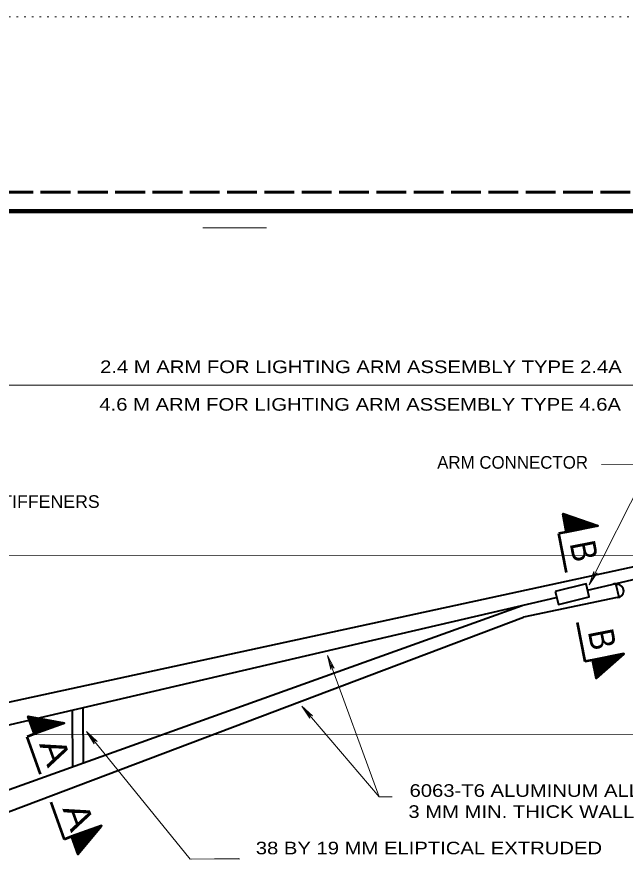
# Model space of a CAD drawing. Extents: x 312583 to 312854, y 144419 to 144597.
# Drawn here: x 312778.8 to 312815.4, y 144545.9 to 144596.8 of the extents above; entities that cross this region are included whole.
import ezdxf
from ezdxf.enums import TextEntityAlignment as Align

# ---------------------------------------------------------------- set-up
doc = ezdxf.new("R2010")
doc.units = 0
doc.header["$LTSCALE"] = 0.3
doc.linetypes.add('DOTTED', pattern=[1.5, 0.3, -1.2])
doc.linetypes.add('LONG_DASHED', pattern=[7.5, 6, -1.5])
for name, color, linetype, lineweight in [('1', 7, 'Continuous', 35), ('2', 7, 'Continuous', 13), ('62', 7, 'DOTTED', 13), ('63', 7, 'LONG_DASHED', 60)]:
    doc.layers.add(name, color=color, linetype=linetype, lineweight=lineweight)

msp = doc.modelspace()

# ---------------------------------------------------------------- linework, layer by layer
at = {"layer": '1', "lineweight": 13}
msp.add_line((312793.8154, 144584.0756), (312789.9897, 144584.0756), dxfattribs=at)
at = {"layer": '1'}
for p, q in [((312811.7094, 144566.8026), (312811.7247, 144566.8256)), ((312811.717, 144566.7643), (312811.7477, 144566.818)), ((312811.7324, 144566.7106), (312811.763, 144566.8103)), ((312811.74, 144566.6646), (312811.7937, 144566.795)), ((312811.7477, 144566.611), (312811.8167, 144566.795)), ((312811.7554, 144566.5726), (312811.832, 144566.7796)), ((312811.763, 144566.519), (312811.855, 144566.7796)), ((312811.7784, 144566.473), (312811.8857, 144566.772)), ((312811.786, 144566.427), (312811.901, 144566.7643)), ((312811.7937, 144566.381), (312811.9317, 144566.7566)), ((312811.8014, 144566.335), (312811.947, 144566.749)), ((312811.809, 144566.289), (312811.97, 144566.7413)), ((312811.8244, 144566.243), (312812.0007, 144566.7336)), ((312811.832, 144566.1893), (312812.016, 144566.726)), ((312811.8397, 144566.1433), (312812.039, 144566.7183)), ((312811.8474, 144566.0973), (312812.0544, 144566.7106)), ((312811.855, 144566.0436), (312812.085, 144566.6953)), ((312811.8704, 144565.9976), (312812.108, 144566.6953)), ((312811.878, 144565.9516), (312812.1234, 144566.68)), ((312811.8857, 144565.9133), (312812.154, 144566.6723)), ((312811.8934, 144565.8596), (312812.177, 144566.6723)), ((312811.901, 144565.8213), (312812.1924, 144566.657)), ((312811.9164, 144565.7676), (312812.223, 144566.657)), ((312811.9317, 144565.7446), (312812.2384, 144566.6416)), ((312811.9624, 144565.7523), (312812.269, 144566.6416)), ((312811.993, 144565.76), (312812.292, 144566.6263)), ((312812.016, 144565.7676), (312812.3074, 144566.6263)), ((312812.0467, 144565.7676), (312812.3304, 144566.611)), ((312812.062, 144565.783), (312812.361, 144566.611)), ((312812.0927, 144565.7906), (312812.3764, 144566.5956)), ((312812.1234, 144565.783), (312812.3994, 144566.5956)), ((312812.1464, 144565.7906), (312812.4224, 144566.588)), ((312812.177, 144565.7983), (312812.4454, 144566.5726)), ((312812.2, 144565.7983), (312812.4684, 144566.5726)), ((312812.2307, 144565.806), (312812.4914, 144566.5573)), ((312812.2614, 144565.8136), (312812.522, 144566.5496)), ((312812.2844, 144565.8136), (312812.5374, 144566.542)), ((312812.315, 144565.829), (312812.5604, 144566.5343)), ((312812.3457, 144565.829), (312812.5834, 144566.5266)), ((312812.3687, 144565.829), (312812.5987, 144566.519)), ((312812.3917, 144565.8366), (312812.6294, 144566.519)), ((312812.4224, 144565.8443), (312812.6524, 144566.5036)), ((312812.453, 144565.852), (312812.6677, 144566.5036)), ((312812.4837, 144565.852), (312812.6907, 144566.4883)), ((312812.5067, 144565.8596), (312812.7137, 144566.4883)), ((312812.5374, 144565.8673), (312812.7367, 144566.473)), ((312812.5527, 144565.875), (312812.7674, 144566.473)), ((312812.591, 144565.875), (312812.7827, 144566.4576)), ((312812.6064, 144565.8826), (312812.8134, 144566.45)), ((312812.637, 144565.8826), (312812.8364, 144566.4423)), ((312812.6677, 144565.8903), (312812.8517, 144566.4346)), ((312812.6907, 144565.898), (312812.8747, 144566.4346)), ((312812.7214, 144565.898), (312812.9054, 144566.4193)), ((312812.752, 144565.9056), (312812.9207, 144566.4193)), ((312812.775, 144565.9133), (312812.9437, 144566.404)), ((312812.8057, 144565.9133), (312812.9667, 144566.404)), ((312812.8364, 144565.921), (312812.9897, 144566.3886)), ((312812.8594, 144565.9286), (312813.0127, 144566.3886)), ((312812.8824, 144565.9286), (312813.0357, 144566.3733)), ((312812.913, 144565.9363), (312813.0587, 144566.3733)), ((312812.9437, 144565.944), (312813.0817, 144566.358)), ((312812.9667, 144565.9516), (312813.1047, 144566.3503)), ((312812.9897, 144565.9516), (312813.1277, 144566.3503)), ((312813.0204, 144565.9593), (312813.143, 144566.335)), ((312813.0434, 144565.967), (312813.1737, 144566.3273)), ((312813.074, 144565.967), (312813.1967, 144566.3196)), ((312813.097, 144565.9746), (312813.212, 144566.312)), ((312813.1277, 144565.9823), (312813.235, 144566.3043)), ((312813.1584, 144565.99), (312813.2657, 144566.2966)), ((312813.1814, 144565.99), (312813.281, 144566.289)), ((312813.212, 144565.9976), (312813.3117, 144566.2813)), ((312813.235, 144565.9976), (312813.327, 144566.2736)), ((312813.2657, 144566.0053), (312813.3577, 144566.266)), ((312813.2964, 144566.013), (312813.3807, 144566.266)), ((312813.3194, 144566.0206), (312813.396, 144566.2506)), ((312813.35, 144566.0206), (312813.419, 144566.2506)), ((312813.3654, 144566.0283), (312813.442, 144566.2353)), ((312813.4037, 144566.036), (312813.465, 144566.2276)), ((312813.4267, 144566.036), (312813.488, 144566.22)), ((312813.4574, 144566.0436), (312813.511, 144566.2123)), ((312813.4804, 144566.0513), (312813.534, 144566.197)), ((312813.511, 144566.059), (312813.557, 144566.197)), ((312813.534, 144566.059), (312813.58, 144566.1893)), ((312813.557, 144566.0666), (312813.603, 144566.1816)), ((312813.5877, 144566.0666), (312813.626, 144566.174)), ((312813.6184, 144566.0743), (312813.649, 144566.1663)), ((312813.649, 144566.082), (312813.672, 144566.1586)), ((312813.672, 144566.082), (312813.6874, 144566.151)), ((312813.7027, 144566.0896), (312813.718, 144566.1433)), ((312813.7257, 144566.0973), (312813.741, 144566.1356)), ((312813.7564, 144566.105), (312813.7564, 144566.128)), ((312813.787, 144566.105), (312813.7794, 144566.1203)), ((312814.684, 144558.2696), (312814.9064, 144558.009)), ((312814.7147, 144558.2696), (312814.9294, 144558.0243)), ((312814.7377, 144558.2773), (312814.937, 144558.032)), ((312814.7684, 144558.285), (312814.9677, 144558.055)), ((312814.7914, 144558.285), (312814.983, 144558.0626)), ((312814.822, 144558.2926), (312814.9984, 144558.0856)), ((312814.8527, 144558.3003), (312815.0214, 144558.101)), ((312814.8757, 144558.3003), (312815.0367, 144558.1163)), ((312814.9064, 144558.308), (312815.052, 144558.1316)), ((312814.9294, 144558.3156), (312815.075, 144558.147)), ((312814.96, 144558.3233), (312815.0904, 144558.1623)), ((312814.983, 144558.3233), (312815.1057, 144558.1776)), ((312815.0137, 144558.331), (312815.1287, 144558.2006)), ((312815.0367, 144558.3386), (312815.144, 144558.216)), ((312815.0674, 144558.3386), (312815.1594, 144558.2236)), ((312815.0904, 144558.3463), (312815.1824, 144558.2466)), ((312815.1134, 144558.3463), (312815.2054, 144558.2543)), ((312815.144, 144558.354), (312815.213, 144558.2773)), ((312815.1747, 144558.3616), (312815.236, 144558.285)), ((312815.2054, 144558.3693), (312815.259, 144558.308)), ((312815.2284, 144558.3693), (312815.2667, 144558.3156)), ((312815.259, 144558.377), (312815.2897, 144558.3386)), ((312815.282, 144558.3846), (312815.3127, 144558.3463)), ((312815.3127, 144558.3846), (312815.3204, 144558.3693)), ((312815.3434, 144558.3923), (312815.3434, 144558.377)), ((312813.4804, 144558.009), (312814.1014, 144557.3036)), ((312813.488, 144558.032), (312814.109, 144557.319)), ((312813.488, 144557.9553), (312814.0707, 144557.2883)), ((312813.4957, 144557.917), (312814.0554, 144557.273)), ((312813.5034, 144557.8633), (312814.04, 144557.2576)), ((312813.511, 144557.8173), (312814.017, 144557.2423)), ((312813.5187, 144558.0396), (312814.132, 144557.3343)), ((312813.5264, 144557.7713), (312814.0094, 144557.2193)), ((312813.5494, 144558.0473), (312814.155, 144557.3496)), ((312813.5724, 144558.0473), (312814.1627, 144557.365)), ((312813.603, 144558.055), (312814.1857, 144557.3803)), ((312813.626, 144558.055), (312814.2087, 144557.3956)), ((312813.6567, 144558.0626), (312814.2164, 144557.411)), ((312813.6797, 144558.0703), (312814.2394, 144557.4263)), ((312813.7104, 144558.078), (312814.2624, 144557.4416)), ((312813.7334, 144558.0856), (312814.27, 144557.457)), ((312813.7564, 144558.0856), (312814.293, 144557.4723)), ((312813.787, 144558.0933), (312814.316, 144557.4953)), ((312813.8177, 144558.101), (312814.3314, 144557.5106)), ((312813.8407, 144558.101), (312814.3467, 144557.5183)), ((312813.8714, 144558.101), (312814.362, 144557.5413)), ((312813.902, 144558.1163), (312814.385, 144557.549)), ((312813.925, 144558.1163), (312814.4004, 144557.572)), ((312813.948, 144558.124), (312814.4234, 144557.5796)), ((312813.9787, 144558.1316), (312814.4387, 144557.6026)), ((312814.0094, 144558.1393), (312814.454, 144557.6103)), ((312814.04, 144558.1393), (312814.4694, 144557.6333)), ((312814.063, 144558.147), (312814.4924, 144557.641)), ((312814.0937, 144558.1546), (312814.5077, 144557.664)), ((312814.1167, 144558.147), (312814.5384, 144557.6793)), ((312814.1397, 144558.1623), (312814.546, 144557.6946)), ((312814.1627, 144558.1623), (312814.569, 144557.71)), ((312814.1934, 144558.17), (312814.5844, 144557.7253)), ((312814.224, 144558.1776), (312814.5997, 144557.7406)), ((312814.247, 144558.1853), (312814.6227, 144557.756)), ((312814.2777, 144558.1853), (312814.638, 144557.7713)), ((312814.3084, 144558.193), (312814.6534, 144557.7866)), ((312814.3314, 144558.2006), (312814.6764, 144557.802)), ((312814.362, 144558.2006), (312814.6917, 144557.8173)), ((312814.3927, 144558.2083), (312814.707, 144557.8326)), ((312814.4157, 144558.216), (312814.73, 144557.848)), ((312814.4387, 144558.216), (312814.7454, 144557.8633)), ((312814.4694, 144558.2236), (312814.7684, 144557.8786)), ((312814.5, 144558.2313), (312814.7837, 144557.894)), ((312814.5307, 144558.239), (312814.799, 144557.917)), ((312814.5537, 144558.239), (312814.822, 144557.9246)), ((312814.5767, 144558.2466), (312814.8374, 144557.9476)), ((312814.5997, 144558.2543), (312814.8527, 144557.963)), ((312814.6304, 144558.2543), (312814.8757, 144557.9783)), ((312814.6534, 144558.262), (312814.8834, 144557.9936)), ((312813.534, 144557.733), (312813.9864, 144557.2116)), ((312813.5417, 144557.6793), (312813.9634, 144557.1886)), ((312813.5494, 144557.6333), (312813.9557, 144557.1733)), ((312813.557, 144557.5873), (312813.9327, 144557.158)), ((312813.5724, 144557.5336), (312813.9174, 144557.1426)), ((312813.58, 144557.4876), (312813.902, 144557.1273)), ((312813.5877, 144557.4416), (312813.879, 144557.112)), ((312813.5954, 144557.388), (312813.8637, 144557.0966)), ((312813.6107, 144557.3496), (312813.8407, 144557.0813)), ((312813.6184, 144557.3036), (312813.8254, 144557.066)), ((312813.626, 144557.2576), (312813.8024, 144557.0506)), ((312813.6337, 144557.204), (312813.787, 144557.0353)), ((312813.6414, 144557.1656), (312813.7717, 144557.02)), ((312813.649, 144557.112), (312813.7487, 144557.0046)), ((312813.6644, 144557.066), (312813.7334, 144556.9893)), ((312813.672, 144557.0123), (312813.718, 144556.9663)), ((312813.6797, 144556.974), (312813.695, 144556.9586)), ((312779.4634, 144554.5896), (312779.471, 144554.6126)), ((312779.4787, 144554.5436), (312779.494, 144554.6126)), ((312779.494, 144554.4976), (312779.517, 144554.605)), ((312779.5094, 144554.4516), (312779.54, 144554.5973)), ((312779.5324, 144554.4056), (312779.563, 144554.5973)), ((312779.54, 144554.3673), (312779.586, 144554.5896)), ((312779.563, 144554.3136), (312779.609, 144554.5896)), ((312779.5784, 144554.2753), (312779.632, 144554.582)), ((312779.5937, 144554.2293), (312779.655, 144554.582)), ((312779.609, 144554.1833), (312779.6857, 144554.5743)), ((312779.6244, 144554.1373), (312779.701, 144554.5743)), ((312779.6397, 144554.0913), (312779.7317, 144554.5666)), ((312779.655, 144554.053), (312779.7547, 144554.5666)), ((312779.678, 144553.9993), (312779.7777, 144554.559)), ((312779.6934, 144553.9533), (312779.8007, 144554.559)), ((312779.7087, 144553.915), (312779.816, 144554.5513)), ((312779.724, 144553.8613), (312779.8467, 144554.5436)), ((312779.7394, 144553.823), (312779.8697, 144554.5436)), ((312779.7547, 144553.777), (312779.885, 144554.536)), ((312779.77, 144553.731), (312779.9157, 144554.5283)), ((312779.793, 144553.685), (312779.9387, 144554.5283)), ((312779.8007, 144553.6466), (312779.9617, 144554.5206)), ((312779.8237, 144553.593), (312779.9924, 144554.5206)), ((312779.8467, 144553.5776), (312780.0077, 144554.513)), ((312779.8697, 144553.593), (312780.0384, 144554.513)), ((312779.9004, 144553.6006), (312780.0614, 144554.5053)), ((312779.9234, 144553.6083), (312780.0767, 144554.5053)), ((312779.954, 144553.616), (312780.1074, 144554.4976)), ((312779.9694, 144553.6313), (312780.1304, 144554.4976)), ((312780, 144553.6466), (312780.1534, 144554.49)), ((312780.023, 144553.6466), (312780.1764, 144554.49)), ((312780.0537, 144553.6543), (312780.1994, 144554.4823)), ((312780.0844, 144553.6696), (312780.2224, 144554.4746)), ((312780.1074, 144553.6773), (312780.2454, 144554.4746)), ((312780.1304, 144553.685), (312780.2684, 144554.467)), ((312780.161, 144553.6926), (312780.299, 144554.4593)), ((312780.184, 144553.7003), (312780.3144, 144554.4593)), ((312780.207, 144553.7233), (312780.345, 144554.4516)), ((312780.2377, 144553.7233), (312780.368, 144554.4516)), ((312780.2607, 144553.731), (312780.3834, 144554.444)), ((312780.2837, 144553.7386), (312780.414, 144554.444)), ((312780.3144, 144553.754), (312780.437, 144554.4363)), ((312780.345, 144553.7616), (312780.4524, 144554.4363)), ((312780.368, 144553.7693), (312780.483, 144554.4286)), ((312780.391, 144553.777), (312780.506, 144554.4286)), ((312780.4217, 144553.7923), (312780.5214, 144554.421)), ((312780.437, 144553.8076), (312780.5597, 144554.4286)), ((312780.4677, 144553.8076), (312780.575, 144554.421)), ((312780.4907, 144553.8153), (312780.6057, 144554.4133)), ((312780.5214, 144553.823), (312780.6287, 144554.4133)), ((312780.552, 144553.8383), (312780.644, 144554.398)), ((312780.575, 144553.846), (312780.6747, 144554.4056)), ((312780.598, 144553.8536), (312780.6977, 144554.398)), ((312780.6287, 144553.869), (312780.713, 144554.398)), ((312780.6517, 144553.8766), (312780.7437, 144554.3903)), ((312780.6824, 144553.8843), (312780.7667, 144554.3903)), ((312780.713, 144553.892), (312780.7897, 144554.3826)), ((312780.7284, 144553.8996), (312780.8127, 144554.3826)), ((312780.7514, 144553.9073), (312780.8357, 144554.375)), ((312780.782, 144553.9226), (312780.8587, 144554.375)), ((312780.8127, 144553.9303), (312780.8817, 144554.3673)), ((312780.8357, 144553.938), (312780.9047, 144554.3596)), ((312780.8587, 144553.9533), (312780.9354, 144554.3596)), ((312780.8894, 144553.961), (312780.9507, 144554.352)), ((312780.9124, 144553.9686), (312780.9814, 144554.3443)), ((312780.943, 144553.9763), (312781.0044, 144554.3443)), ((312780.9584, 144553.984), (312781.0197, 144554.3366)), ((312780.989, 144553.9993), (312781.0504, 144554.3366)), ((312781.0197, 144554.007), (312781.0734, 144554.329)), ((312781.0427, 144554.0146), (312781.0887, 144554.329)), ((312781.0657, 144554.0223), (312781.127, 144554.3213)), ((312781.0887, 144554.03), (312781.1424, 144554.3213)), ((312781.1194, 144554.0453), (312781.1654, 144554.3136)), ((312781.15, 144554.053), (312781.196, 144554.3136)), ((312781.173, 144554.0606), (312781.2114, 144554.306)), ((312781.196, 144554.076), (312781.2344, 144554.306)), ((312781.219, 144554.0836), (312781.265, 144554.2983)), ((312781.2497, 144554.0913), (312781.2804, 144554.2906)), ((312781.2804, 144554.099), (312781.311, 144554.2906)), ((312781.3034, 144554.1143), (312781.334, 144554.283)), ((312781.3264, 144554.122), (312781.357, 144554.2753)), ((312781.357, 144554.1296), (312781.38, 144554.2753)), ((312781.38, 144554.1373), (312781.403, 144554.2676)), ((312781.403, 144554.145), (312781.426, 144554.2676)), ((312781.426, 144554.1603), (312781.449, 144554.26)), ((312781.4567, 144554.168), (312781.472, 144554.26)), ((312781.4874, 144554.1756), (312781.5027, 144554.2523)), ((312781.5104, 144554.1833), (312781.518, 144554.2523)), ((312781.541, 144554.1986), (312781.541, 144554.2446)), ((312781.5564, 144554.2063), (312781.5717, 144554.2446)), ((312781.587, 144554.214), (312781.587, 144554.237)), ((312781.6177, 144554.2216), (312781.61, 144554.237)), ((312782.5837, 144547.5746), (312783.105, 144547.13)), ((312782.6144, 144547.5823), (312783.128, 144547.153)), ((312782.6374, 144547.59), (312783.1434, 144547.1683)), ((312782.668, 144547.6053), (312783.151, 144547.1836)), ((312782.691, 144547.6053), (312783.1817, 144547.2066)), ((312782.714, 144547.6206), (312783.1894, 144547.222)), ((312782.737, 144547.6283), (312783.2047, 144547.245)), ((312782.7677, 144547.6436), (312783.22, 144547.2603)), ((312782.7984, 144547.6513), (312783.2354, 144547.2756)), ((312782.8214, 144547.659), (312783.2507, 144547.2986)), ((312782.8444, 144547.6666), (312783.266, 144547.314)), ((312782.875, 144547.682), (312783.2814, 144547.3293)), ((312782.898, 144547.6896), (312783.2967, 144547.3523)), ((312782.9287, 144547.6973), (312783.3197, 144547.3676)), ((312782.9517, 144547.705), (312783.3274, 144547.383)), ((312782.9747, 144547.7203), (312783.3427, 144547.3983)), ((312782.9977, 144547.728), (312783.358, 144547.4213)), ((312783.0284, 144547.7356), (312783.381, 144547.4366)), ((312783.059, 144547.7433), (312783.3887, 144547.4596)), ((312783.082, 144547.7586), (312783.404, 144547.4826)), ((312783.105, 144547.7663), (312783.427, 144547.498)), ((312783.1357, 144547.774), (312783.4347, 144547.5133)), ((312783.1587, 144547.7816), (312783.45, 144547.5363)), ((312783.1894, 144547.7893), (312783.4654, 144547.5516)), ((312783.2047, 144547.797), (312783.4807, 144547.5746)), ((312783.2354, 144547.8123), (312783.496, 144547.59)), ((312783.266, 144547.82), (312783.5114, 144547.613)), ((312783.289, 144547.8276), (312783.5267, 144547.6206)), ((312783.312, 144547.843), (312783.5497, 144547.6436)), ((312783.335, 144547.8506), (312783.5574, 144547.659)), ((312783.3657, 144547.8583), (312783.5727, 144547.682)), ((312783.3964, 144547.866), (312783.5957, 144547.6973)), ((312783.4194, 144547.8736), (312783.6034, 144547.7203)), ((312783.4424, 144547.889), (312783.6264, 144547.728)), ((312783.4654, 144547.8966), (312783.6417, 144547.751)), ((312783.496, 144547.9043), (312783.6494, 144547.774)), ((312783.5267, 144547.912), (312783.6647, 144547.7893)), ((312783.5497, 144547.9273), (312783.6877, 144547.8123)), ((312783.5727, 144547.935), (312783.6954, 144547.8276)), ((312783.6034, 144547.9426), (312783.7107, 144547.843)), ((312783.6264, 144547.9503), (312783.726, 144547.866)), ((312783.6494, 144547.958), (312783.749, 144547.8813)), ((312783.6724, 144547.9733), (312783.7567, 144547.9043)), ((312783.703, 144547.981), (312783.772, 144547.9196)), ((312783.7337, 144547.9886), (312783.795, 144547.9426)), ((312783.7567, 144547.9963), (312783.8027, 144547.9503)), ((312783.7797, 144548.0116), (312783.818, 144547.9733)), ((312783.8027, 144548.0193), (312783.841, 144547.9886)), ((312783.8334, 144548.027), (312783.8487, 144548.0116)), ((312783.864, 144548.0423), (312783.864, 144548.027)), ((312782.0854, 144547.3676), (312782.806, 144546.7696)), ((312782.093, 144547.3906), (312782.8214, 144546.785)), ((312782.1007, 144547.314), (312782.783, 144546.7466)), ((312782.116, 144547.406), (312782.8367, 144546.8003)), ((312782.116, 144547.2833), (312782.7754, 144546.7313)), ((312782.1314, 144547.2296), (312782.7524, 144546.716)), ((312782.1467, 144547.4136), (312782.852, 144546.8233)), ((312782.1467, 144547.1836), (312782.737, 144546.693)), ((312782.162, 144547.1453), (312782.7294, 144546.67)), ((312782.1697, 144547.4213), (312782.8674, 144546.8386)), ((312782.1774, 144547.0993), (312782.7064, 144546.6546)), ((312782.2004, 144547.4366), (312782.8827, 144546.854)), ((312782.2234, 144547.4366), (312782.898, 144546.8693)), ((312782.254, 144547.4443), (312782.9057, 144546.8923)), ((312782.2694, 144547.4596), (312782.9287, 144546.9076)), ((312782.3, 144547.4673), (312782.944, 144546.9306)), ((312782.3307, 144547.4826), (312782.9517, 144546.946)), ((312782.346, 144547.4903), (312782.9747, 144546.9613)), ((312782.3767, 144547.498), (312782.99, 144546.9843)), ((312782.4074, 144547.5056), (312783.0054, 144547.0073)), ((312782.4304, 144547.5133), (312783.0207, 144547.0226)), ((312782.461, 144547.521), (312783.036, 144547.0456)), ((312782.484, 144547.5363), (312783.0514, 144547.061)), ((312782.507, 144547.544), (312783.059, 144547.0763)), ((312782.53, 144547.5516), (312783.082, 144547.0916)), ((312782.5607, 144547.567), (312783.0974, 144547.1146)), ((312782.2004, 144547.0533), (312782.691, 144546.6316)), ((312782.2157, 144547.0073), (312782.6834, 144546.6163)), ((312782.231, 144546.9613), (312782.668, 144546.601)), ((312782.2464, 144546.9153), (312782.6527, 144546.578)), ((312782.2617, 144546.8693), (312782.6374, 144546.5626)), ((312782.277, 144546.8233), (312782.622, 144546.5396)), ((312782.3, 144546.7773), (312782.6067, 144546.532)), ((312782.3154, 144546.7313), (312782.5837, 144546.509)), ((312782.3307, 144546.693), (312782.576, 144546.4936)), ((312782.346, 144546.647), (312782.5607, 144546.4706)), ((312782.3614, 144546.5933), (312782.5377, 144546.4553)), ((312782.3767, 144546.5626), (312782.53, 144546.4323)), ((312782.392, 144546.509), (312782.507, 144546.417)), ((312782.415, 144546.463), (312782.4917, 144546.4016)), ((312782.4304, 144546.417), (312782.484, 144546.3786)), ((312782.4457, 144546.371), (312782.4687, 144546.3633))]:
    msp.add_line(p, q, dxfattribs=at)
at = {"layer": '1', "lineweight": 53}
for p, q in [((312811.9164, 144565.7446), (312811.4487, 144565.6526)), ((312811.9087, 144563.3066), (312811.4487, 144565.6526)), ((312812.5527, 144560.286), (312813.005, 144557.94)), ((312813.4727, 144558.032), (312813.005, 144557.94)), ((312779.8314, 144553.5776), (312779.3867, 144553.409)), ((312780.1994, 144551.1626), (312779.3867, 144553.409)), ((312780.8127, 144549.476), (312781.633, 144547.222)), ((312782.0777, 144547.3906), (312781.633, 144547.222))]:
    msp.add_line(p, q, dxfattribs=at)
at = {"layer": '1', "lineweight": 40}
for p, q in [((312770.2404, 144553.754), (312816.4474, 144563.7743)), ((312813.166, 144562.2333), (312816.846, 144563.092)), ((312814.8834, 144562.586), (312815.0597, 144561.8116)), ((312770.2864, 144552.259), (312811.2954, 144561.7963)), ((312814.9677, 144561.7963), (312809.325, 144560.608)), ((312770.3247, 144547.3676), (312809.233, 144561.3133)), ((312770.386, 144545.9033), (312809.325, 144560.608)), ((312782.1467, 144551.6073), (312782.1314, 144555.0036)), ((312782.783, 144551.822), (312782.7677, 144555.1646))]:
    msp.add_line(p, q, dxfattribs=at)
at = {"layer": '1', "lineweight": 158}
msp.add_lwpolyline([(312616.5, 144423.1446), (312616.5, 144585.0846), (312849, 144585.0846)], dxfattribs=at)
at = {"layer": '1', "lineweight": 53}
for points in [[(312811.9164, 144565.7446), (312811.7017, 144566.8333), (312813.7947, 144566.1126)], [(312813.4727, 144558.032), (312813.6874, 144556.9433), (312815.3587, 144558.4)], [(312779.8314, 144553.5776), (312779.448, 144554.6203), (312781.633, 144554.2293)], [(312782.0777, 144547.3906), (312782.4534, 144546.3403), (312783.8794, 144548.0423)]]:
    msp.add_lwpolyline(points, close=True, dxfattribs=at)
at = {"layer": '1', "lineweight": 40}
msp.add_lwpolyline([(312811.2264, 144562.1566), (312811.4257, 144561.3823), (312813.281, 144561.85), (312813.0894, 144562.6243)], close=True, dxfattribs=at)
msp.add_arc((312814.9655, 144562.1924), 0.3969, 270, 90, dxfattribs=at)
msp.add_spline([(312814.9677, 144562.5936), (312814.8527, 144562.632), (312814.707, 144562.586)], degree=3, dxfattribs=at)
at = {"layer": '2'}
for p, q in [((312828.5454, 144574.5996), (312769.2667, 144574.5843)), ((312816.9457, 144569.831), (312813.2657, 144562.5553)), ((312816.9457, 144569.831), (312814.0247, 144569.8156)), ((312840.996, 144564.3416), (312755.1677, 144564.311)), ((312813.2657, 144562.5553), (312813.557, 144563.3756)), ((312813.557, 144563.3756), (312813.5264, 144563.0843)), ((312813.2657, 144562.5553), (312813.7487, 144563.2836)), ((312813.7487, 144563.2836), (312813.5264, 144563.0843)), ((312797.5107, 144558.3156), (312797.71, 144557.4646)), ((312797.5107, 144558.3156), (312797.9094, 144557.5413)), ((312797.5107, 144558.3156), (312797.71, 144557.4646)), ((312797.5107, 144558.3156), (312797.9094, 144557.5413)), ((312797.71, 144557.4646), (312797.71, 144557.7636)), ((312797.9094, 144557.5413), (312797.71, 144557.7636)), ((312797.71, 144557.4646), (312797.71, 144557.7636)), ((312797.9094, 144557.5413), (312797.71, 144557.7636)), ((312800.608, 144549.7826), (312795.9467, 144555.2566)), ((312795.9467, 144555.2566), (312796.4297, 144554.5283)), ((312795.9467, 144555.2566), (312796.5907, 144554.6663)), ((312796.4297, 144554.5283), (312796.33, 144554.812)), ((312796.5907, 144554.6663), (312796.33, 144554.812)), ((312789.2307, 144546.0336), (312782.9824, 144553.731)), ((312782.9824, 144553.731), (312783.4424, 144552.9873)), ((312782.9824, 144553.731), (312783.611, 144553.1253)), ((312840.9884, 144553.547), (312779.5554, 144553.5316)), ((312783.4424, 144552.9873), (312783.3504, 144553.271)), ((312783.611, 144553.1253), (312783.3504, 144553.271)), ((312792.1517, 144546.0643), (312789.2307, 144546.0413)), ((312792.2207, 144546.049), (312789.2997, 144546.0336))]:
    msp.add_line(p, q, dxfattribs=at)
msp.add_lwpolyline([(312801.39, 144549.7903), (312800.608, 144549.7826), (312797.5107, 144558.3156)], dxfattribs=at)
at = {"layer": '62'}
msp.add_line((312601.2, 144596.7846), (312853.5, 144596.7846), dxfattribs=at)
at = {"layer": '63'}
msp.add_line((312851.75, 144586.2246), (312583.526, 144586.2246), dxfattribs=at)

# ---------------------------------------------------------------- texts
at = {"layer": '1'}
for s, height, rotation, width, p in [('B', 1.533, 281.005, 0.9, (312812.2112, 144564.4608)), ('B', 1.534, 281.005, 0.9, (312813.3075, 144559.1401)), ('A', 1.533, 289.986, 1.15, (312780.3717, 144552.2298)), ('A', 1.533, 290.004, 1.15, (312781.7826, 144548.3351))]:
    msp.add_text(s, height=height, rotation=rotation, dxfattribs=dict(at, width=width)).set_placement(p, align=Align.CENTER)
at = {"layer": '2'}
for s, width, p in [('2.4 M ARM FOR LIGHTING ARM ASSEMBLY TYPE 2.4A', 1.2, (312783.792, 144575.3232)), ('4.6 M ARM FOR LIGHTING ARM ASSEMBLY TYPE 4.6A', 1.2, (312783.7456, 144573.0576)), ('STIFFENERS', 1.05, (312777.1268, 144567.2013)), ('6063-T6 ALUMINUM ALLOY', 1.2, (312802.4466, 144549.7894)), ('3 MM MIN. THICK WALL', 1.2, (312802.3766, 144548.5197)), ('38 BY 19 MM ELIPTICAL EXTRUDED', 1.2, (312793.1775, 144546.326))]:
    msp.add_text(s, height=0.76, dxfattribs=dict(at, width=width)).set_placement(p)
msp.add_text('ARM CONNECTOR', height=0.76, dxfattribs=at).set_placement((312804.114, 144569.5617))

doc.saveas('drawing.dxf')
